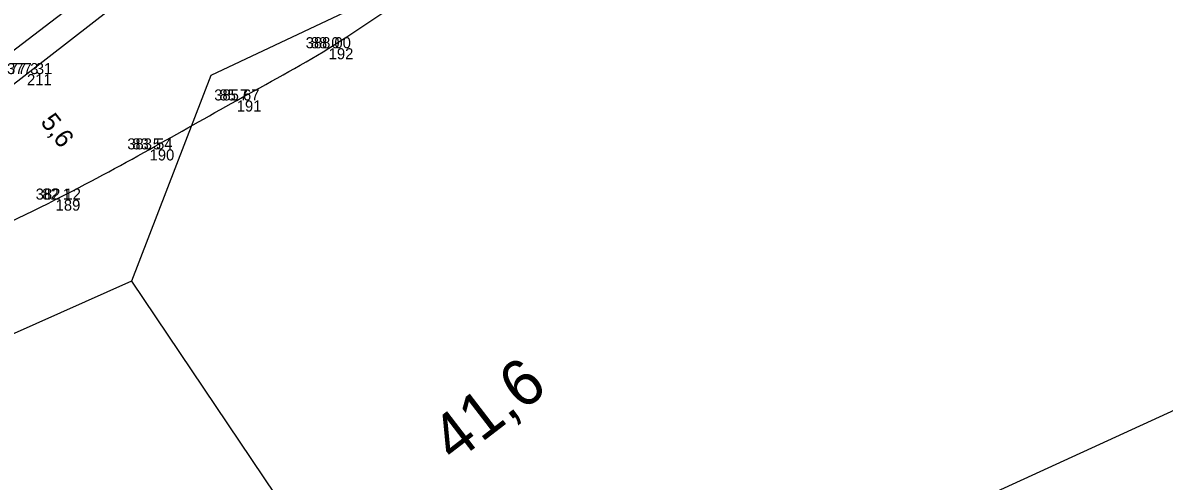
# Model space of a CAD drawing. Extents: x -514509 to -512782, y -1144610 to -1143439.
# Drawn here: x -514055.3 to -513931.4, y -1144214.7 to -1144165 of the extents above; entities that cross this region are included whole.
import ezdxf

# ---------------------------------------------------------------- set-up
doc = ezdxf.new("R2010")
doc.units = 0
for name, color, linetype in [('Vrstva 10', 7, 'Continuous'), ('Vrstva 11', 7, 'Continuous'), ('Vrstva 57', 7, 'Continuous'), ('Vrstva 58', 7, 'Continuous'), ('Vrstva 59', 7, 'Continuous'), ('Vrstva 6', 7, 'Continuous'), ('Vrstva 60', 7, 'Continuous'), ('Vrstva 7', 7, 'Continuous'), ('Vrstva 8', 7, 'Continuous')]:
    doc.layers.add(name, color=color, linetype=linetype)

msp = doc.modelspace()

# ---------------------------------------------------------------- linework, layer by layer
at = {"layer": 'Vrstva 10'}
for points in [[(-513950.819, -1144116.604), (-514000.894, -1144154.698), (-514034.859, -1144170.712), (-514043.464, -1144193.045), (-514082.363, -1144210.357), (-514102.508, -1144218.103), (-514125.814, -1144226.26), (-514151.34, -1144249.937), (-514141.201, -1144262.004), (-514150.898, -1144269.151), (-514166.094, -1144270.501), (-514200.74, -1144295.636)], [(-513950.819, -1144116.604), (-514000.894, -1144154.698), (-514034.859, -1144170.712), (-514043.464, -1144193.045), (-514082.363, -1144210.357), (-514102.508, -1144218.103), (-514125.814, -1144226.26), (-514151.34, -1144249.937), (-514141.201, -1144262.004), (-514150.898, -1144269.151), (-514166.094, -1144270.501), (-514200.74, -1144295.636)], [(-514040.943, -1144159.737), (-514054.814, -1144170.559), (-514066, -1144179.202), (-514075.579, -1144186.694)]]:
    msp.add_lwpolyline(points, dxfattribs=at)
for points in [[(-514064.866, -1144190.49), (-514051.703, -1144184.182), (-514041.505, -1144178.728), (-514032.041, -1144173.42), (-514022.058, -1144167.753), (-514011.721, -1144160.773), (-513999.222, -1144151.227), (-513992.592, -1144144.354), (-513988.289, -1144139.161), (-513982.052, -1144133.709), (-513972.955, -1144126.776), (-513961.884, -1144118.324), (-513951.972, -1144108.242)], [(-514089.153, -1144183.779), (-514079.972, -1144177.241), (-514069.241, -1144169.508), (-514058.557, -1144161.338), (-514051.55, -1144155.553), (-514045.934, -1144149.911), (-514041.516, -1144145.196), (-514037.177, -1144139.013), (-514028.69, -1144130.171), (-514018.868, -1144122.197), (-514006.697, -1144112.04)]]:
    msp.add_spline(points, degree=3, dxfattribs=at)
at = {"layer": 'Vrstva 6'}
msp.add_lwpolyline([(-514059.172, -1144170.185), (-514048.99, -1144162.375), (-514042.739, -1144157.579), (-514042.112, -1144157.098), (-514032.184, -1144149.482), (-514021.429, -1144141.232), (-514010.88, -1144133.14), (-514000.44, -1144125.131), (-513990.338, -1144117.382), (-513979.751, -1144109.26), (-513969.477, -1144101.379)], dxfattribs=at)
at = {"layer": 'Vrstva 60'}
for p, q in [((-514022.06, -1144167.75), (-514022.06, -1144167.75)), ((-514054.81, -1144170.56), (-514054.81, -1144170.56)), ((-514032.04, -1144173.42), (-514032.04, -1144173.42)), ((-514041.5, -1144178.73), (-514041.5, -1144178.73)), ((-514051.7, -1144184.18), (-514051.7, -1144184.18))]:
    msp.add_line(p, q, dxfattribs=at)
at = {"layer": 'Vrstva 8'}
msp.add_lwpolyline([(-514043.464, -1144193.045), (-514009.606, -1144243.364), (-513890.389, -1144188.771), (-513889.626, -1144194.796)], dxfattribs=at)

# ---------------------------------------------------------------- texts
at = {"layer": 'Vrstva 11'}
msp.add_text('5,6', height=2, rotation=307.69324, dxfattribs=at).set_placement((-514053.42, -1144175.774))
at = {"layer": 'Vrstva 57'}
for s, p in [('88 0 ', (-514024.008, -1144167.75)), ('77 3 ', (-514056.693, -1144170.56)), ('85 7 ', (-514033.923, -1144173.42)), ('83 5 ', (-514043.383, -1144178.73)), ('82 1 ', (-514053.158, -1144184.18))]:
    msp.add_text(s, height=1.2, dxfattribs=at).set_placement(p)
at = {"layer": 'Vrstva 58'}
for s, p in [('388 00', (-514024.558, -1144167.75)), ('377 31', (-514056.976, -1144170.56)), ('385 67', (-514034.486, -1144173.42)), ('383 54', (-514043.921, -1144178.73)), ('382 12', (-514053.866, -1144184.18))]:
    msp.add_text(s, height=1.2, dxfattribs=at).set_placement(p)
at = {"layer": 'Vrstva 59'}
for s, p in [('192', (-514022.06, -1144168.95)), ('211', (-514054.81, -1144171.76)), ('191', (-514032.04, -1144174.62)), ('190', (-514041.5, -1144179.93)), ('189', (-514051.7, -1144185.38))]:
    msp.add_text(s, height=1.2, dxfattribs=at).set_placement(p)
at = {"layer": 'Vrstva 7'}
msp.add_text('41,6', height=5, rotation=37.53453, dxfattribs=at).set_placement((-514008.444, -1144212.863))

doc.saveas('drawing.dxf')
